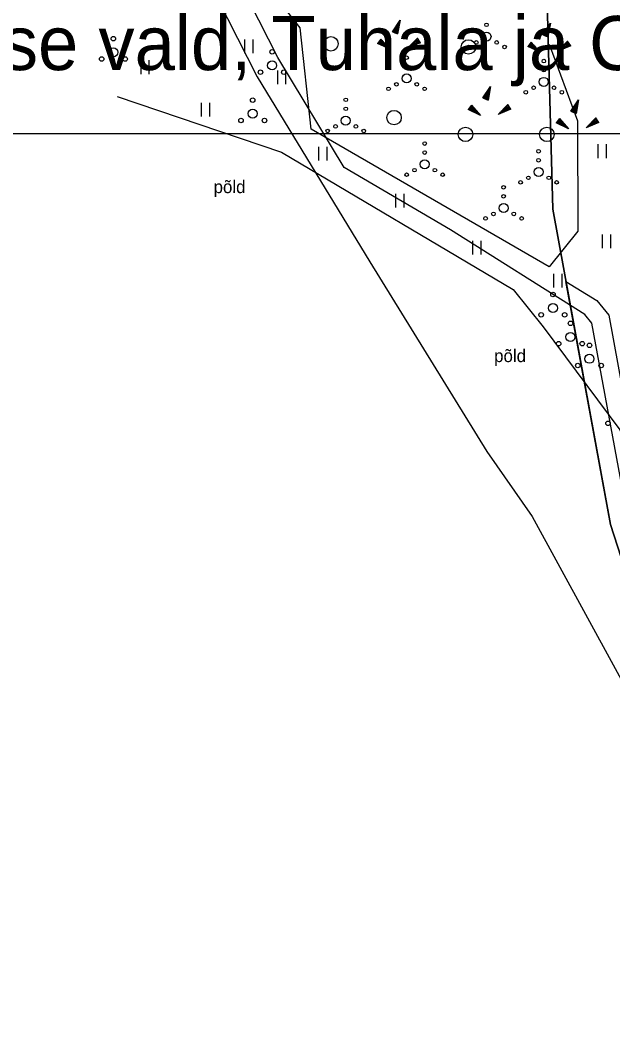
# Model space of a CAD drawing. Extents: x 554947 to 555436, y 6564938 to 6565792.
# Drawn here: x 555027.7 to 555060.6, y 6565555.5 to 6565611.2 of the extents above; entities that cross this region are included whole.
import ezdxf

# ---------------------------------------------------------------- set-up
doc = ezdxf.new("R2010")
doc.units = 0
for name, color, linetype in [('HALJASTUS', 7, 'Continuous'), ('KASUTUSALA', 7, 'Continuous'), ('KPKAABEL', 7, 'Continuous'), ('PIIR', 7, 'Continuous'), ('PR_SIDE', 7, 'Continuous'), ('PUU', 7, 'Continuous'), ('RELJEEF', 7, 'Continuous'), ('VORMISTUS_2', 7, 'Continuous')]:
    doc.layers.add(name, color=color, linetype=linetype)

msp = doc.modelspace()

# ---------------------------------------------------------------- linework, layer by layer
at = {"layer": 'HALJASTUS'}
for p, q in [((555040.145, 6565610.116), (555040.145, 6565609.355)), ((555040.6, 6565610.116), (555040.6, 6565609.355)), ((555034.383, 6565608.969), (555034.383, 6565608.208)), ((555034.838, 6565608.969), (555034.838, 6565608.208)), ((555041.957, 6565608.406), (555041.957, 6565607.645)), ((555042.412, 6565608.406), (555042.412, 6565607.645)), ((555037.737, 6565606.607), (555037.737, 6565605.846)), ((555038.192, 6565606.607), (555038.192, 6565605.846)), ((555044.239, 6565604.173), (555044.239, 6565603.412)), ((555044.694, 6565604.173), (555044.694, 6565603.412)), ((555059.719, 6565604.314), (555059.719, 6565603.553)), ((555060.174, 6565604.314), (555060.174, 6565603.553)), ((555048.509, 6565601.572), (555048.509, 6565600.811)), ((555048.964, 6565601.572), (555048.964, 6565600.811)), ((555059.968, 6565599.32), (555059.968, 6565598.559)), ((555060.423, 6565599.32), (555060.423, 6565598.559)), ((555052.779, 6565598.971), (555052.779, 6565598.209)), ((555053.234, 6565598.971), (555053.234, 6565598.209)), ((555057.264, 6565597.135), (555057.264, 6565596.374)), ((555057.719, 6565597.135), (555057.719, 6565596.374))]:
    msp.add_line(p, q, dxfattribs=at)
for points in [[(555057.023, 6565609.855), (555058.586, 6565605.616), (555058.613, 6565599.497), (555057.015, 6565597.532), (555043.839, 6565605.146), (555043.23, 6565610.761), (555037.198, 6565618.427), (555042.201, 6565623.493), (555040.415, 6565628.763), (555044.392, 6565634.613), (555048.032, 6565636.033)], [(555033.078, 6565606.955), (555042.182, 6565603.884), (555055.024, 6565596.272), (555056.694, 6565594.201), (555060.942, 6565588.507), (555062.867, 6565584.513)]]:
    msp.add_lwpolyline(points, dxfattribs=at)
for centre, radius in [((555053.549, 6565610.933), 0.1), ((555044.928, 6565609.882), 0.4), ((555053.549, 6565610.283), 0.25), ((555052.549, 6565609.708), 0.4), ((555052.549, 6565609.708), 0.1), ((555052.984, 6565609.958), 0.1), ((555054.114, 6565609.958), 0.1), ((555054.549, 6565609.708), 0.1), ((555049.12, 6565609.112), 0.1), ((555049.12, 6565608.612), 0.1), ((555056.725, 6565608.924), 0.1), ((555049.12, 6565607.962), 0.25), ((555056.725, 6565607.774), 0.25), ((555056.725, 6565608.424), 0.1), ((555048.12, 6565607.387), 0.1), ((555048.555, 6565607.637), 0.1), ((555049.685, 6565607.637), 0.1), ((555050.12, 6565607.387), 0.1), ((555056.16, 6565607.449), 0.1), ((555057.29, 6565607.449), 0.1), ((555055.725, 6565607.199), 0.1), ((555057.725, 6565607.199), 0.1), ((555045.748, 6565606.779), 0.1), ((555045.748, 6565606.279), 0.1), ((555045.748, 6565605.629), 0.25), ((555048.425, 6565605.793), 0.4), ((555045.183, 6565605.304), 0.1), ((555046.313, 6565605.304), 0.1), ((555052.386, 6565604.865), 0.4), ((555056.894, 6565604.865), 0.4), ((555044.748, 6565605.054), 0.1), ((555046.748, 6565605.054), 0.1), ((555050.122, 6565604.356), 0.1), ((555050.122, 6565603.856), 0.1), ((555056.435, 6565603.933), 0.1), ((555050.122, 6565603.206), 0.25), ((555056.435, 6565602.783), 0.25), ((555056.435, 6565603.433), 0.1), ((555049.122, 6565602.631), 0.1), ((555049.557, 6565602.881), 0.1), ((555050.687, 6565602.881), 0.1), ((555051.122, 6565602.631), 0.1), ((555055.87, 6565602.458), 0.1), ((555057, 6565602.458), 0.1), ((555054.496, 6565601.934), 0.1), ((555055.435, 6565602.208), 0.1), ((555057.435, 6565602.208), 0.1), ((555054.496, 6565601.434), 0.1), ((555054.496, 6565600.784), 0.25), ((555053.496, 6565600.209), 0.1), ((555053.931, 6565600.459), 0.1), ((555055.061, 6565600.459), 0.1), ((555055.496, 6565600.209), 0.1)]:
    msp.add_circle(centre, radius, dxfattribs=at)
at = {"layer": 'KASUTUSALA'}
msp.add_lwpolyline([(555144.16, 6565410.6), (555124.27, 6565454.45), (555113.82, 6565475.68), (555076.76, 6565542.38), (555065.78, 6565566.7), (555060.42, 6565583.26), (555057.954, 6565596.723), (555059.656, 6565595.654), (555060.33, 6565594.851), (555062.363, 6565583.75), (555067.552, 6565567.72), (555071.198, 6565559.537), (555075.701, 6565550.483), (555082.19, 6565538.355), (555091.441, 6565521.624), (555102.427, 6565501.094), (555109.9, 6565486.829), (555116.169, 6565475.57), (555126.773, 6565453.774), (555135.197, 6565435.201)], dxfattribs=at)
at = {"layer": 'KPKAABEL'}
msp.add_lwpolyline([(555022.085, 6565654.913), (555021.622, 6565652.627), (555021.526, 6565649.765), (555022.786, 6565647.231), (555026.485, 6565641.465), (555030.606, 6565629.728), (555035.378, 6565618.813), (555040.844, 6565608.057), (555047.089, 6565597.805), (555053.567, 6565587.292), (555056.073, 6565583.696), (555062.108, 6565572.667), (555068.248, 6565560.982), (555073.771, 6565549.852), (555080.106, 6565537.978), (555085.958, 6565527.605), (555092.403, 6565515.607), (555098.402, 6565504.536), (555104.641, 6565492.438), (555110.839, 6565480.82), (555116.697, 6565469.072), (555121.821, 6565458.116), (555126.894, 6565446.731), (555132.737, 6565435.388)], dxfattribs=at)
at = {"layer": 'PIIR'}
for points in [[(555016.055, 6565654.913), (555030.24, 6565648.23), (555043.11, 6565640.11), (555053.62, 6565632.14), (555056.61, 6565622.91), (555057.22, 6565600.73), (555060.42, 6565583.26), (555065.78, 6565566.7), (555076.76, 6565542.38), (555113.82, 6565475.68), (554946.63, 6565420.78), (554981.01, 6565316.76), (555160.07, 6565375.54), (555166.64, 6565360.5), (555167.67, 6565357.913)], [(555144.16, 6565410.6), (555124.27, 6565454.45), (555113.82, 6565475.68), (555076.76, 6565542.38), (555065.78, 6565566.7), (555060.42, 6565583.26), (555057.22, 6565600.73), (555056.61, 6565622.91), (555063.43, 6565647.29), (555114.24, 6565634), (555129.77, 6565611.2), (555130.73, 6565621.32), (555138.66, 6565615.26), (555160.12, 6565598.86), (555193.24, 6565604.68), (555193.7, 6565602.7), (555225.47, 6565605.89), (555234.35, 6565605.6), (555251.24, 6565598.48), (555330.71, 6565538.85), (555343.81, 6565536.56), (555350.68, 6565540.44), (555361.56, 6565549.57), (555393.069, 6565582.099)]]:
    msp.add_lwpolyline(points, dxfattribs=at)
at = {"layer": 'PR_SIDE'}
msp.add_lwpolyline([(555074.812, 6565550.025), (555070.293, 6565559.111), (555066.617, 6565567.361), (555061.392, 6565583.505), (555059.394, 6565594.411), (555058.991, 6565594.89), (555051.547, 6565599.57), (555045.662, 6565603.031), (555041.98, 6565609.132), (555036.735, 6565619.454), (555032.194, 6565629.84), (555030.448, 6565634.707), (555030.925, 6565637.158), (555034.991, 6565644.113), (555043.172, 6565658.105), (555043.563, 6565658.774), (555046.326, 6565658.494), (555056.182, 6565651.59), (555064.179, 6565647.804), (555084.437, 6565642.829), (555092.497, 6565648.433), (555092.737, 6565648.737), (555092.881, 6565649.42), (555093.272, 6565650.246)], dxfattribs=at)
at = {"layer": 'PUU'}
for centre, radius in [((555032.872, 6565610.163), 0.125), ((555032.222, 6565609.038), 0.125), ((555032.872, 6565609.413), 0.25), ((555033.522, 6565609.038), 0.125), ((555041.669, 6565609.433), 0.125), ((555041.669, 6565608.683), 0.25), ((555041.019, 6565608.308), 0.125), ((555042.319, 6565608.308), 0.125), ((555040.593, 6565606.763), 0.125), ((555040.593, 6565606.013), 0.25), ((555039.943, 6565605.638), 0.125), ((555041.243, 6565605.638), 0.125), ((555057.23, 6565595.993), 0.125), ((555057.23, 6565595.243), 0.25), ((555056.579, 6565594.868), 0.125), ((555057.88, 6565594.868), 0.125), ((555058.203, 6565594.394), 0.125), ((555058.203, 6565593.644), 0.25), ((555057.552, 6565593.269), 0.125), ((555058.853, 6565593.269), 0.125), ((555059.256, 6565593.182), 0.125), ((555059.256, 6565592.432), 0.25), ((555058.606, 6565592.057), 0.125), ((555059.906, 6565592.057), 0.125), ((555060.284, 6565588.861), 0.125)]:
    msp.add_circle(centre, radius, dxfattribs=at)
at = {"layer": 'RELJEEF'}
for p, q in [((555048.34, 6565610.548), (555048.76, 6565611.188)), ((555048.44, 6565610.698), (555048.69, 6565610.803)), ((555048.49, 6565610.773), (555048.615, 6565610.828)), ((555048.54, 6565610.848), (555048.71, 6565610.923)), ((555048.59, 6565610.923), (555048.72, 6565610.983)), ((555048.615, 6565610.828), (555048.7, 6565610.863)), ((555048.76, 6565611.188), (555048.62, 6565610.433)), ((555048.635, 6565610.998), (555048.735, 6565611.038)), ((555048.685, 6565611.073), (555048.745, 6565611.098)), ((555048.735, 6565611.148), (555048.755, 6565611.158)), ((555056.668, 6565610.381), (555057.088, 6565611.021)), ((555056.918, 6565610.756), (555057.048, 6565610.816)), ((555057.088, 6565611.021), (555056.948, 6565610.266)), ((555056.963, 6565610.831), (555057.063, 6565610.871)), ((555057.013, 6565610.906), (555057.073, 6565610.931)), ((555057.063, 6565610.981), (555057.083, 6565610.991)), ((555048.34, 6565610.548), (555048.665, 6565610.688)), ((555048.34, 6565610.548), (555048.62, 6565610.433)), ((555048.34, 6565610.548), (555048.34, 6565610.548)), ((555048.39, 6565610.623), (555048.675, 6565610.743)), ((555048.405, 6565610.523), (555048.655, 6565610.628)), ((555048.47, 6565610.493), (555048.645, 6565610.568)), ((555048.54, 6565610.468), (555048.635, 6565610.508)), ((555048.605, 6565610.443), (555048.62, 6565610.448)), ((555056.668, 6565610.381), (555056.993, 6565610.521)), ((555056.668, 6565610.381), (555056.948, 6565610.266)), ((555056.668, 6565610.381), (555056.668, 6565610.381)), ((555056.718, 6565610.456), (555057.003, 6565610.576)), ((555056.733, 6565610.356), (555056.983, 6565610.461)), ((555056.768, 6565610.531), (555057.018, 6565610.636)), ((555056.798, 6565610.326), (555056.973, 6565610.401)), ((555056.818, 6565610.606), (555056.943, 6565610.661)), ((555056.868, 6565610.681), (555057.038, 6565610.756)), ((555056.868, 6565610.301), (555056.963, 6565610.341)), ((555056.933, 6565610.276), (555056.948, 6565610.281)), ((555056.943, 6565610.661), (555057.028, 6565610.696)), ((555047.698, 6565610.147), (555047.513, 6565609.907)), ((555048.203, 6565609.577), (555047.513, 6565609.907)), ((555047.523, 6565609.922), (555047.528, 6565609.902)), ((555047.568, 6565609.977), (555047.583, 6565609.877)), ((555047.613, 6565610.037), (555047.638, 6565609.852)), ((555047.653, 6565610.092), (555047.688, 6565609.822)), ((555047.698, 6565610.147), (555048.203, 6565609.577)), ((555047.698, 6565610.147), (555047.743, 6565609.797)), ((555047.698, 6565610.147), (555047.698, 6565610.147)), ((555047.758, 6565610.082), (555047.798, 6565609.772)), ((555047.818, 6565610.012), (555047.853, 6565609.747)), ((555047.878, 6565609.947), (555047.893, 6565609.807)), ((555047.893, 6565609.807), (555047.908, 6565609.717)), ((555047.933, 6565609.877), (555047.963, 6565609.692)), ((555047.993, 6565609.812), (555048.013, 6565609.667)), ((555048.053, 6565609.742), (555048.068, 6565609.642)), ((555048.113, 6565609.677), (555048.123, 6565609.612)), ((555049.177, 6565609.642), (555049.717, 6565610.187)), ((555049.887, 6565609.937), (555049.177, 6565609.642)), ((555049.302, 6565609.692), (555049.242, 6565609.707)), ((555049.387, 6565609.727), (555049.282, 6565609.747)), ((555049.467, 6565609.762), (555049.327, 6565609.792)), ((555049.552, 6565609.797), (555049.367, 6565609.832)), ((555049.502, 6565609.857), (555049.412, 6565609.877)), ((555049.717, 6565609.867), (555049.452, 6565609.917)), ((555049.802, 6565609.902), (555049.497, 6565609.962)), ((555049.637, 6565609.832), (555049.502, 6565609.857)), ((555049.887, 6565609.937), (555049.537, 6565610.002)), ((555049.847, 6565609.992), (555049.582, 6565610.047)), ((555049.807, 6565610.052), (555049.622, 6565610.087)), ((555049.767, 6565610.112), (555049.667, 6565610.132)), ((555049.727, 6565610.172), (555049.707, 6565610.172)), ((555049.887, 6565609.937), (555049.717, 6565610.187)), ((555049.887, 6565609.937), (555049.887, 6565609.937)), ((555056.027, 6565609.98), (555055.842, 6565609.74)), ((555056.532, 6565609.41), (555055.842, 6565609.74)), ((555055.852, 6565609.755), (555055.857, 6565609.735)), ((555055.897, 6565609.81), (555055.912, 6565609.71)), ((555055.942, 6565609.87), (555055.967, 6565609.685)), ((555055.982, 6565609.925), (555056.017, 6565609.655)), ((555056.027, 6565609.98), (555056.532, 6565609.41)), ((555056.027, 6565609.98), (555056.072, 6565609.63)), ((555056.027, 6565609.98), (555056.027, 6565609.98)), ((555056.087, 6565609.915), (555056.127, 6565609.605)), ((555056.147, 6565609.845), (555056.182, 6565609.58)), ((555056.207, 6565609.78), (555056.222, 6565609.64)), ((555056.262, 6565609.71), (555056.292, 6565609.525)), ((555057.506, 6565609.475), (555058.046, 6565610.02)), ((555058.216, 6565609.77), (555057.506, 6565609.475)), ((555057.831, 6565609.69), (555057.741, 6565609.71)), ((555058.046, 6565609.7), (555057.781, 6565609.75)), ((555058.131, 6565609.735), (555057.826, 6565609.795)), ((555057.966, 6565609.665), (555057.831, 6565609.69)), ((555058.216, 6565609.77), (555057.866, 6565609.835)), ((555058.176, 6565609.825), (555057.911, 6565609.88)), ((555058.136, 6565609.885), (555057.951, 6565609.92)), ((555058.096, 6565609.945), (555057.996, 6565609.965)), ((555058.056, 6565610.005), (555058.036, 6565610.005)), ((555058.216, 6565609.77), (555058.046, 6565610.02)), ((555058.216, 6565609.77), (555058.216, 6565609.77)), ((555048.173, 6565609.607), (555048.178, 6565609.587)), ((555049.217, 6565609.657), (555049.202, 6565609.662)), ((555056.222, 6565609.64), (555056.237, 6565609.55)), ((555056.322, 6565609.645), (555056.342, 6565609.5)), ((555056.382, 6565609.575), (555056.397, 6565609.475)), ((555056.442, 6565609.51), (555056.452, 6565609.445)), ((555056.502, 6565609.44), (555056.507, 6565609.42)), ((555057.546, 6565609.49), (555057.531, 6565609.495)), ((555057.631, 6565609.525), (555057.571, 6565609.54)), ((555057.716, 6565609.56), (555057.611, 6565609.58)), ((555057.796, 6565609.595), (555057.656, 6565609.625)), ((555057.881, 6565609.63), (555057.696, 6565609.665)), ((555053.353, 6565606.88), (555053.773, 6565607.52)), ((555053.773, 6565607.52), (555053.633, 6565606.765)), ((555053.748, 6565607.48), (555053.768, 6565607.49)), ((555053.353, 6565606.88), (555053.678, 6565607.02)), ((555053.403, 6565606.955), (555053.688, 6565607.075)), ((555053.418, 6565606.855), (555053.668, 6565606.96)), ((555053.453, 6565607.03), (555053.703, 6565607.135)), ((555053.483, 6565606.825), (555053.658, 6565606.9)), ((555053.503, 6565607.105), (555053.628, 6565607.16)), ((555053.553, 6565607.18), (555053.723, 6565607.255)), ((555053.603, 6565607.255), (555053.733, 6565607.315)), ((555053.628, 6565607.16), (555053.713, 6565607.195)), ((555053.648, 6565607.33), (555053.748, 6565607.37)), ((555053.698, 6565607.405), (555053.758, 6565607.43)), ((555052.712, 6565606.48), (555052.527, 6565606.24)), ((555052.627, 6565606.37), (555052.652, 6565606.185)), ((555052.667, 6565606.425), (555052.702, 6565606.155)), ((555052.712, 6565606.48), (555053.217, 6565605.91)), ((555052.712, 6565606.48), (555052.757, 6565606.13)), ((555052.712, 6565606.48), (555052.712, 6565606.48)), ((555052.772, 6565606.415), (555052.812, 6565606.105)), ((555052.832, 6565606.345), (555052.867, 6565606.08)), ((555053.353, 6565606.88), (555053.633, 6565606.765)), ((555053.353, 6565606.88), (555053.353, 6565606.88)), ((555053.553, 6565606.8), (555053.648, 6565606.84)), ((555053.618, 6565606.775), (555053.633, 6565606.78)), ((555054.191, 6565605.975), (555054.731, 6565606.52)), ((555054.901, 6565606.27), (555054.551, 6565606.335)), ((555054.861, 6565606.325), (555054.596, 6565606.38)), ((555054.821, 6565606.385), (555054.636, 6565606.42)), ((555054.781, 6565606.445), (555054.681, 6565606.465)), ((555054.741, 6565606.505), (555054.721, 6565606.505)), ((555054.901, 6565606.27), (555054.731, 6565606.52)), ((555058.231, 6565606.142), (555058.651, 6565606.782)), ((555058.281, 6565606.217), (555058.566, 6565606.337)), ((555058.331, 6565606.292), (555058.581, 6565606.397)), ((555058.381, 6565606.367), (555058.506, 6565606.422)), ((555058.431, 6565606.442), (555058.601, 6565606.517)), ((555058.481, 6565606.517), (555058.611, 6565606.577)), ((555058.506, 6565606.422), (555058.591, 6565606.457)), ((555058.651, 6565606.782), (555058.511, 6565606.027)), ((555058.526, 6565606.592), (555058.626, 6565606.632)), ((555058.576, 6565606.667), (555058.636, 6565606.692)), ((555058.626, 6565606.742), (555058.646, 6565606.752)), ((555053.217, 6565605.91), (555052.527, 6565606.24)), ((555052.537, 6565606.255), (555052.542, 6565606.235)), ((555052.582, 6565606.31), (555052.597, 6565606.21)), ((555052.892, 6565606.28), (555052.907, 6565606.14)), ((555052.907, 6565606.14), (555052.922, 6565606.05)), ((555052.947, 6565606.21), (555052.977, 6565606.025)), ((555053.007, 6565606.145), (555053.027, 6565606)), ((555053.067, 6565606.075), (555053.082, 6565605.975)), ((555053.127, 6565606.01), (555053.137, 6565605.945)), ((555053.187, 6565605.94), (555053.192, 6565605.92)), ((555054.901, 6565606.27), (555054.191, 6565605.975)), ((555054.231, 6565605.99), (555054.216, 6565605.995)), ((555054.316, 6565606.025), (555054.256, 6565606.04)), ((555054.401, 6565606.06), (555054.296, 6565606.08)), ((555054.481, 6565606.095), (555054.341, 6565606.125)), ((555054.566, 6565606.13), (555054.381, 6565606.165)), ((555054.516, 6565606.19), (555054.426, 6565606.21)), ((555054.731, 6565606.2), (555054.466, 6565606.25)), ((555054.816, 6565606.235), (555054.511, 6565606.295)), ((555054.651, 6565606.165), (555054.516, 6565606.19)), ((555054.901, 6565606.27), (555054.901, 6565606.27)), ((555058.231, 6565606.142), (555058.556, 6565606.282)), ((555058.231, 6565606.142), (555058.511, 6565606.027)), ((555058.231, 6565606.142), (555058.231, 6565606.142)), ((555058.296, 6565606.117), (555058.546, 6565606.222)), ((555058.361, 6565606.087), (555058.536, 6565606.162)), ((555058.431, 6565606.062), (555058.526, 6565606.102)), ((555058.496, 6565606.037), (555058.511, 6565606.042)), ((555059.069, 6565605.236), (555059.609, 6565605.781)), ((555059.779, 6565605.531), (555059.609, 6565605.781)), ((555057.59, 6565605.741), (555057.405, 6565605.501)), ((555058.095, 6565605.171), (555057.405, 6565605.501)), ((555057.415, 6565605.516), (555057.42, 6565605.496)), ((555057.46, 6565605.571), (555057.475, 6565605.471)), ((555057.505, 6565605.631), (555057.53, 6565605.446)), ((555057.545, 6565605.686), (555057.58, 6565605.416)), ((555057.59, 6565605.741), (555058.095, 6565605.171)), ((555057.59, 6565605.741), (555057.635, 6565605.391)), ((555057.59, 6565605.741), (555057.59, 6565605.741)), ((555057.65, 6565605.676), (555057.69, 6565605.366)), ((555057.71, 6565605.606), (555057.745, 6565605.341)), ((555057.77, 6565605.541), (555057.785, 6565605.401)), ((555057.785, 6565605.401), (555057.8, 6565605.311)), ((555057.825, 6565605.471), (555057.855, 6565605.286)), ((555057.885, 6565605.406), (555057.905, 6565605.261)), ((555057.945, 6565605.336), (555057.96, 6565605.236)), ((555058.005, 6565605.271), (555058.015, 6565605.206)), ((555059.779, 6565605.531), (555059.069, 6565605.236)), ((555059.109, 6565605.251), (555059.094, 6565605.256)), ((555059.194, 6565605.286), (555059.134, 6565605.301)), ((555059.279, 6565605.321), (555059.174, 6565605.341)), ((555059.359, 6565605.356), (555059.219, 6565605.386)), ((555059.444, 6565605.391), (555059.259, 6565605.426)), ((555059.394, 6565605.451), (555059.304, 6565605.471)), ((555059.609, 6565605.461), (555059.344, 6565605.511)), ((555059.694, 6565605.496), (555059.389, 6565605.556)), ((555059.529, 6565605.426), (555059.394, 6565605.451)), ((555059.779, 6565605.531), (555059.429, 6565605.596)), ((555059.739, 6565605.586), (555059.474, 6565605.641)), ((555059.699, 6565605.646), (555059.514, 6565605.681)), ((555059.659, 6565605.706), (555059.559, 6565605.726)), ((555059.619, 6565605.766), (555059.599, 6565605.766)), ((555059.779, 6565605.531), (555059.779, 6565605.531)), ((555058.065, 6565605.201), (555058.07, 6565605.181))]:
    msp.add_line(p, q, dxfattribs=at)
at = {"layer": 'VORMISTUS_2'}
msp.add_lwpolyline([(555186.863, 6565394.913), (555021.863, 6565394.913), (555021.863, 6565604.913), (555186.863, 6565604.913)], close=True, dxfattribs=at)

# ---------------------------------------------------------------- texts
at = {"layer": 'HALJASTUS'}
for p in [(555038.423, 6565601.611), (555053.97, 6565592.252)]:
    msp.add_text('põld', height=0.7, rotation=359.9544, dxfattribs=at).set_placement(p)
at = {"layer": 'VORMISTUS_2'}
msp.add_text('Kose vald, Tuhala ja Otiveski elurajooni sideühendus', height=3, rotation=360, dxfattribs=at).set_placement((555021.782, 6565608.425))

doc.saveas('drawing.dxf')
